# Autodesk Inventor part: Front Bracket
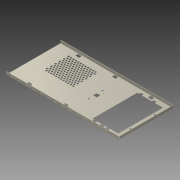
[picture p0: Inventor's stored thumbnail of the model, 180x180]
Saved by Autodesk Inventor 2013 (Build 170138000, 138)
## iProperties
Created: 2007-02
Part Number: Front Bracket
Material: Allgemein
Document SubType Name: Sheet Metal
Designer: Autodesk, Inc.
Mass: 56.0258 g
Surface Area: 1172.88 cm^2
Volume: 56.0258 cm^3
Density: 1 g/cm^3
Flat Pattern Width: 19.4953 cm
Flat Pattern Length: 37.6477 cm
Flat Pattern Area: 733.953 cm^2
Sheet Metal Rule: 1 mm
Sheet Metal Width: 194.953 mm
Sheet Metal Length: 376.477 mm
Sheet Metal Area: 73395.269 mm^2
Author: Autodesk, Inc.
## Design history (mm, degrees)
node "Face1"
node "Flange1"
feature "iFeature5:1" dims "d28" = 1, "d29" = 2.5 (= 0.5 x d30), "d30" = 5, "d31" = 6, "d32" = 1, "d33" = 0.5, "d34" = 3 (= 0.5 x d31), "d35" = 1 (= d32)
sketch "Sketch4"
  geometry: L1 (-138, -73)-(-138, -79); L2 (-129, -73)-(-138, -73); L3 (-129, -79)-(-129, -73); L4 (-138, -79)-(-129, -79); L5 (-123, -73)-(-165, -73); L6 (-129, 73)-(-138, 73); L7 (-123, 73)-(-123, -73); L8 (-165, -73)-(-165, 73); L9 (-165, 73)-(-123, 73); L10 (-138, 79)-(-129, 79); L11 (-138, 73)-(-138, 79); L12 (-129, 79)-(-129, 73); L13 (-184, -87.293)-(-184, 87.293) reference; L14 (184, -89)-(-182.293, -89) reference
  constraints: 24 end point, 6 parallel, 3 collinear, 3 horizontal, 3 perpendicular, 2 point on line
  dimensions: "d46" = 146 distance of L5.end L8.end; "d48" = 9 distance of L10.start L10.end; "d49" = 27 distance between parallel lines of L8 L11; "d50" = 42 distance between parallel lines of L7 L8; "d51" = 19 distance between parallel lines of L13 L8; "d52" = 16 distance between parallel lines of L14 L5
cut "Cut1" sketch "Sketch4" dims "d53" = 1 (= Thickness), "d54" = 0
pattern_linear "Rectangular Pattern1" dims "d57" = 42
cut "Cut2" dims "d66" = 1 (= Thickness), "d67" = 0
node "Flange2"
feature "iFeature6:1" dims "d88" = 6
feature "iFeature6:2" dims "d92" = 6
feature "iFeature9:1" dims "d96" = 2.5
feature "iFeature8:1" dims "d100" = 5
feature "iFeature7:1" dims "d103" = 12 (= d104), "d104" = 12
body "Solid1"
sketch "Sketch1"
  geometry: L1 (-184, 89)-(184, 89); L2 (184, 89)-(184, -89); L3 (184, -89)-(-184, -89); L4 (-184, -89)-(-184, 89); L5 (-184, 89)-(184, -89); 2 further points
  constraints: 10 end point, 2 parallel, 1 coincident, 1 horizontal, 1 midpoint, 1 perpendicular
  dimensions: "d0" = 368 distance of L2.end L3.end; "d1" = 178 distance of L3.end L1.start
face "Plate1" dims "Thickness" = 1
sketch "Sketch2"
  geometry: L1 through (-184, 0) direction (1, 0); L2 through (0, 5) direction (0, 1); L3 (0, 10)-(-368, 10); L4 (-368, 10)-(-368, 0)
  constraints: 6 end point, 1 horizontal, 1 perpendicular, 1 vertical
face "Plate2" dims "d3" = 1 (= BendReliefWidth), "d4" = 0.5 (= BendReliefDepth), "d5" = 2 (= MinimumRemnant), "d6" = 0.5 (= BendRadius), "d7" = 10, "d8" = 90 deg, "d9" = 0.5 (= BendRadius), "d10" = 4 (= CornerReliefSize), "d11" = 1 (= Thickness), "d106" = 1 (= JacobiRadiusSize), "SeamGap" = 0.01, "Thickness" = 1
bend "Bend1" dims "d3" = 1 (= BendReliefWidth), "d4" = 0.5 (= BendReliefDepth), "d5" = 2 (= MinimumRemnant), "d6" = 0.5 (= BendRadius), "d7" = 10, "d8" = 90 deg, "d9" = 0.5 (= BendRadius), "SeamGap" = 0.01, "Thickness" = 1
feature "Corner1" dims "d7" = 10, "d8" = 90 deg, "d10" = 4 (= CornerReliefSize), "d11" = 1 (= Thickness), "d106" = 1 (= JacobiRadiusSize)
sketch "Sketch3" dims "d19" = 10, "d26" = 10
  geometry: L1 (0, 0)-(0, 8.5) reference; L2 (0, 8.5)-(366.293, 8.5) reference; 29 further points
  constraints: 2 horizontal, 28 other
  dimensions: "d12" = 18 distance from line of point (18, 4.5) L1; "d13" = 4 distance from line of L2 point (18, 4.5); "d16" = 330 distance of point (18, 4.5) point (348, 4.5); "d23" = 23.571 distance of point (18, 4.5) point (41.571, 4.5)
sketch "Sketch5"
  geometry: L1 (-123.5, 83.5)-(-111.5, 83.5); L2 (-111.5, 83.5)-(-111.5, 77.5); L3 (-111.5, 77.5)-(-123.5, 77.5); L4 (-123.5, 77.5)-(-123.5, 83.5); L5 (-184, -87.293)-(-184, 87.293) reference; L6 (-182.293, 89)-(184, 89) reference; L7 (-6, 83.5)-(6, 83.5); L8 (6, 83.5)-(6, 77.5); L9 (6, 77.5)-(-6, 77.5); L10 (-6, 77.5)-(-6, 83.5); L11 (113, 83.5)-(125, 83.5); L12 (125, 83.5)-(125, 77.5); L13 (125, 77.5)-(113, 77.5); L14 (113, 77.5)-(113, 83.5); L15 (257.6, 0)-(-257.6, 0) reference; L16 (-111.5, -83.5)-(-111.5, -77.5); L17 (-123.5, -83.5)-(-111.5, -83.5); L18 (-111.5, -77.5)-(-123.5, -77.5); L19 (-123.5, -77.5)-(-123.5, -83.5); L20 (-6, -77.5)-(-6, -83.5); L21 (-6, -83.5)-(6, -83.5); L22 (6, -77.5)-(-6, -77.5); L23 (6, -83.5)-(6, -77.5); L24 (113, -77.5)-(113, -83.5); L25 (125, -83.5)-(125, -77.5); L26 (113, -83.5)-(125, -83.5); L27 (125, -77.5)-(113, -77.5); 4 further points
  constraints: 48 end point, 14 symmetric about line, 6 parallel, 4 point on line, 3 horizontal, 3 perpendicular, 2 collinear, 2 midpoint
  dimensions: "d58" = 12 distance of L2.end L3.end; "d59" = 6 distance of L3.end L1.start; "d60" = 60.5 distance between parallel lines of L5 L4; "d61" = 5.5 distance between parallel lines of L6 L1; "d62" = 12 distance of L8.end L9.end; "d63" = 12 distance of L12.end L13.end; "d64" = 117.5 distance between parallel lines of L10 L4; "d65" = 119 distance between parallel lines of L14 L10
sketch "Sketch6"
  geometry: L1 (-11.99, 0)-(-0.01, 0); L2 (-0.01, 0)-(-0.01, 5); L3 (-0.01, 5)-(-11.99, 5); L4 (-11.99, 5)-(-11.99, 0)
  constraints: 8 end point
face "Plate3" dims "d68" = 1 (= BendReliefWidth), "d69" = 0.5 (= BendReliefDepth), "d70" = 2 (= MinimumRemnant), "d71" = 0.5 (= BendRadius), "d72" = 5, "d73" = 90 deg, "d74" = 0.5 (= BendRadius), "d75" = 4 (= CornerReliefSize), "d76" = 1 (= Thickness), "d107" = 1 (= JacobiRadiusSize), "SeamGap" = 0.01, "Thickness" = 1
bend "Bend2" dims "d68" = 1 (= BendReliefWidth), "d69" = 0.5 (= BendReliefDepth), "d70" = 2 (= MinimumRemnant), "d71" = 0.5 (= BendRadius), "d72" = 5, "d73" = 90 deg, "d74" = 0.5 (= BendRadius), "SeamGap" = 0.01, "Thickness" = 1
feature "Corner2" dims "d72" = 5, "d73" = 90 deg, "d75" = 4 (= CornerReliefSize), "d76" = 1 (= Thickness), "d107" = 1 (= JacobiRadiusSize)
sketch "Sketch7"
  geometry: L1 (184, -87.5)-(184, 87.5) reference; L2 (-182.293, 89)-(184, 89) reference; L3 (130, 57.072)-(126, 64); L4 (126, 64)-(134, 64); L5 (134, 64)-(130, 57.072); 145 further points
  constraints: 6 end point, 2 coincident, 2 horizontal, 1 vertical, 149 other
  dimensions: "d77" = 50 distance from line of point (134, 64) L1; "d78" = 25 distance from line of L2 point (134, 64); "d79" = 8 distance of L3.end L4.end; "d82" = 8 distance of point (134, 64) point (126, 64); "d85" = 13.856 distance of point (134, 64) point (134, 50.144)
sketch "Sketch8"
  geometry: L1 (-172, 40)-(-172, -40); L2 (-184, -87.293)-(-184, 87.293) reference; L3 (257.6, 0)-(-257.6, 0) reference; 1 further point
  constraints: 2 end point, 1 midpoint, 1 point on line, 1 vertical
  dimensions: "d90" = 80 distance of L1.start L1.end; "d91" = 12 distance from line of L2 L1.start
sketch "Sketch9"
  geometry: L1 (-29, 15)-(-29, -15); L2 (-184, -87.293)-(-184, 87.293) reference; L3 (257.6, 0)-(-257.6, 0) reference; 1 further point
  constraints: 2 end point, 1 midpoint, 1 point on line, 1 vertical
  dimensions: "d94" = 30 distance of L1.start L1.end; "d95" = 155 distance from line of L2 L1.start
sketch "Sketch10"
  geometry: L1 (-18.5, -22.5)-(-18.5, 22.5); L2 (-184, -87.293)-(-184, 87.293) reference; L3 (257.6, 0)-(-257.6, 0) reference; 1 further point
  constraints: 2 end point, 1 midpoint, 1 point on line, 1 vertical
  dimensions: "d98" = 45 distance of L1.start L1.end; "d99" = 165.5 distance from line of L2 L1.end
sketch "Sketch11"
  geometry: L1 (257.6, 0)-(-257.6, 0) reference; L2 (-184, -87.293)-(-184, 87.293) reference; 1 further point
  constraints: 1 point on line
  dimensions: "d102" = 162 distance from line of L2 point (-22, 0)
feature "Definition1" dims "d0" = 1 (derived)
other parameters: "BendRadius" = 0.5, "BendReliefWidth" = 1 (= Thickness), "BendReliefDepth" = 0.5 (= 0.5 x Thickness), "CornerReliefSize" = 4 (= 4 x Thickness), "MinimumRemnant" = 2 (= 2 x Thickness), "TransitionRadius" = 0.5 (= BendRadius), "JacobiRadiusSize" = 1 (= Thickness), "d2" = 0.5 (= BendRadius), "d37" = -90 deg, "d89" = 0, "d93" = 0, "d97" = 0, "d101" = 0, "d105" = 0, "GapSize" = 1 (= Thickness), "BendRadius" = 0.5, "BendReliefDepth" = 0.5, "BendReliefWidth" = 1, "CornerReliefSize" = 4, "JacobiRadiusSize" = 1, "MinimumRemnant" = 2, "Thickness" = 1, "TransitionRadius" = 0.5, "GapSize" = 1
